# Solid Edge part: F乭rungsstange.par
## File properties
Username: bmolnar
Dokumentum tartalom típus: 0
Author: bmolnar
Last saved by: bmolnar
Revision: 77
Sűrűség: 0,000 kg/m^3
Pontosság: 0,990
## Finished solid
Body 1: solid body, 8 faces, 7 edges, 5 vertices.
  Faces by surface: cone 4, cylinder 2, plane 2
  Edges by curve: circle 7
Bounding box of the edges (mm): 8.000 x 8.000 x 72.000, from (-4, -4, -38.5) to (4, 4, 33.5).
Cylindrical faces by radius (mm): R2.067 x1, R4 x1
Conical faces (half-angle, radius in mm at the cone's reference point): 45 deg R2.217 x1, 45 deg R3.5 x1, 45 deg R3.9 x1, 59 deg R1.0335 x1
Planar faces by outward normal: +z 1, -z 1
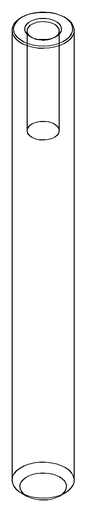
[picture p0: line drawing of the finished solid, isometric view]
